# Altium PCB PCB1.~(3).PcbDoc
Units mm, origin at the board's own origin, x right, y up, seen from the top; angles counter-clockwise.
Board outline 49.47 x 17.47 mm, 4 copper layers (Top Layer, Layer 1, Layer 2, Bottom Layer), stack 0.127 mm thick; 1 components, 1 nets, 2 pads, 3 vias.
Unrouted connection lines stored in the file: 4.
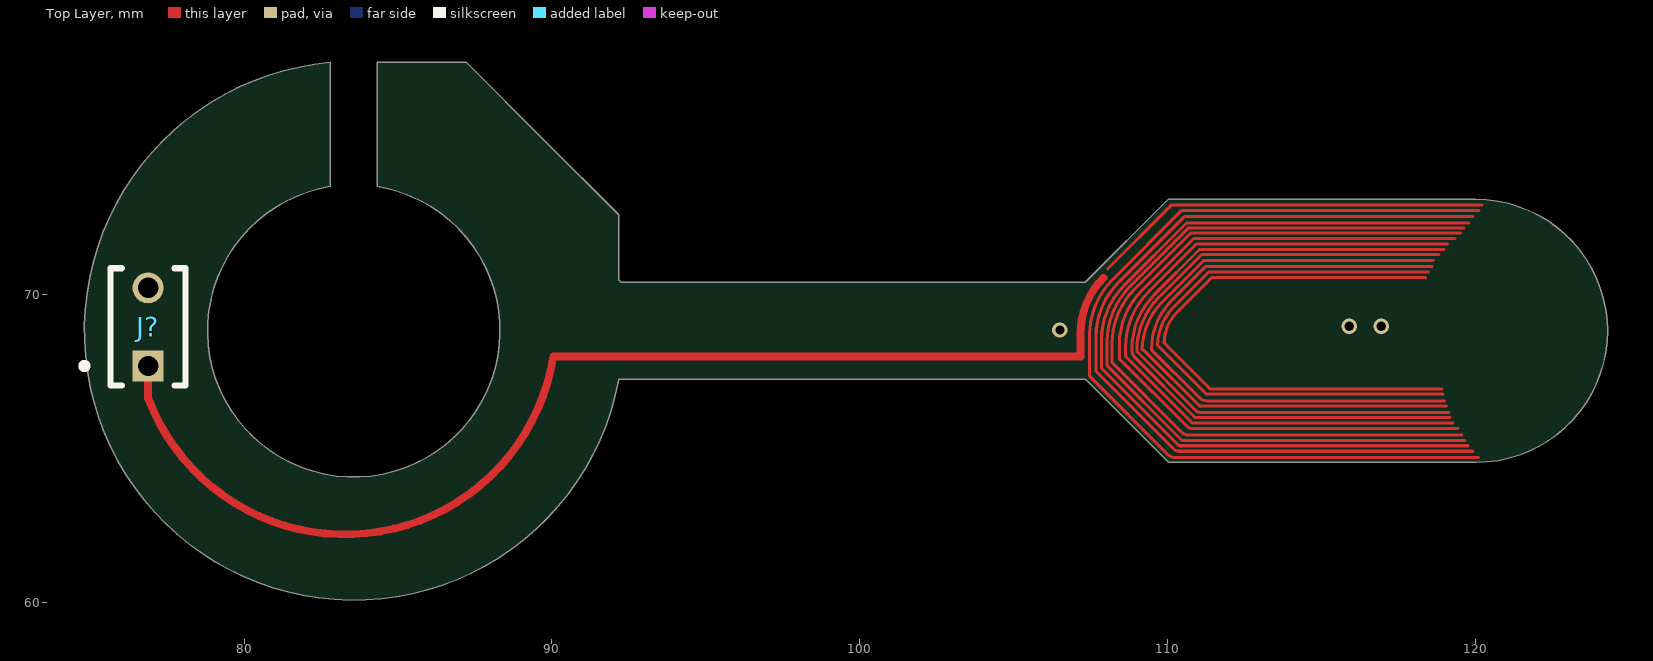
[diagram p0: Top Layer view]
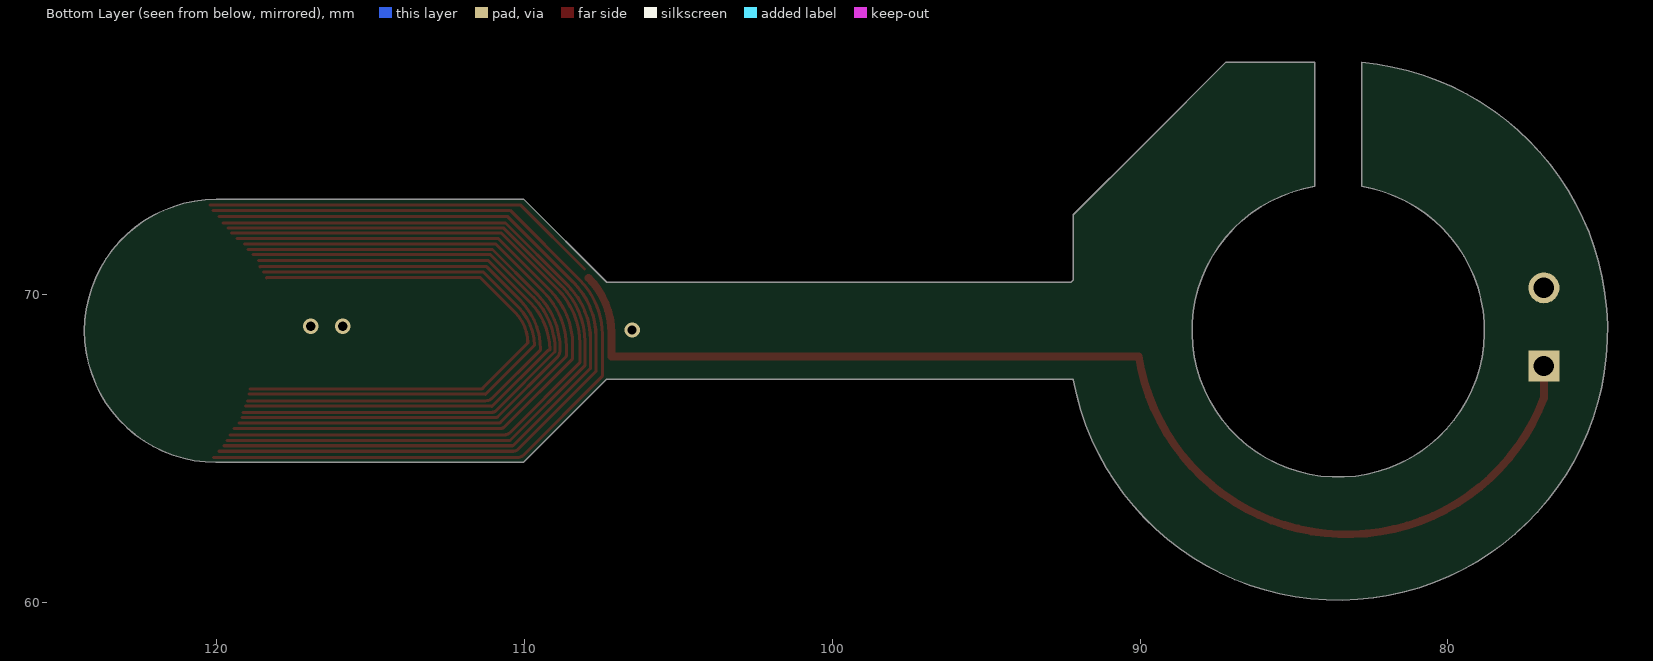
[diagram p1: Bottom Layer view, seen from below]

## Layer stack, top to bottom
Top Solder: solder mask 0.0102, Solder Resist, Dk 3.5
Top Layer: signal copper 0.0127
Dielectric 2: prepreg 0.0254, PP-006, Dk 3.5
Layer 1: signal copper 0.0127
Dielectric 1: dielectric 0.0254, FR-4, Dk 3.5
Layer 2: signal copper 0.0127
Dielectric 3: prepreg 0.0254, PP-006, Dk 3.5
Bottom Layer: signal copper 0.0127
Bottom Solder: solder mask 0.0102, Solder Resist, Dk 3.5

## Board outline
82.805,73.523 ccw(c83.566,68.834) 84.327,73.523 84.329,73.534 84.329,77.551 87.224,77.551 89.753,75.021 92.171,72.604 92.171,70.483 92.245,70.409 107.326,70.409 110.018,73.101 120.018,73.101 cw(c120.021,68.831) 120.021,64.561 120.021,64.57 110.021,64.57 107.332,67.259 92.183,67.259 92.171,67.245 cw(c83.566,68.834) 82.803,77.551

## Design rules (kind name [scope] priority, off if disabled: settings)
Clearance [All] p1: gap=0.254 ignorepadtopadclearanceinfootprint=FALSE except(0: Arc-Hole Track-Hole SMDPad-Hole THPad-Hole Via-Hole Fill-Hole Poly-Hole Region-Hole Text-Hole; 0.06: Arc-Arc Arc-Track Track-Track)
PolygonConnect [All] p1: connectstyle=Relief reliefconductorwidth=0.254 reliefentries=4 polygonreliefangle="90 Angle" airgapwidth=0.254
RoutingVias [All] p1: holewidth=0.711 width=1.27 viastyle="Through Hole" minholewidth=0.711 minwidth=1.27 maxholewidth=0.711 maxwidth=1.27
SolderMaskExpansion [All] p1: expansion=0.102 istentingtop=FALSE
Width [All] p1: maxlimit=0.254 minlimit=0.1 preferedwidth=0.1 minimp=50.000000 maximp=50.000000 favimp=50.000000
30 further rules are at their usual default settings.

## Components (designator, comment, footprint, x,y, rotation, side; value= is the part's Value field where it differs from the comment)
J? "TMS-103-59-L-S-002" SAMTEC_TMS-103-59-L-S-002 76.886,68.961 r90 top

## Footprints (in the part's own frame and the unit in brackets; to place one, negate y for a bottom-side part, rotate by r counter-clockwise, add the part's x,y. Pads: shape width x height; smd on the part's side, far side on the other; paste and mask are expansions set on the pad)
SAMTEC_TMS-103-59-L-S-002 [mm]
  rect 1.01x1.01 hole 0.66: 01(-1.27,0)
  round 1.01 hole 0.66: 03(1.27,0)
  silkscreen extent -1.91,-1.22 1.91,2.17

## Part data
J?: Package=None

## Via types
v1: diameter 0.5, hole 0.3, Top Layer to Bottom Layer, 3 vias

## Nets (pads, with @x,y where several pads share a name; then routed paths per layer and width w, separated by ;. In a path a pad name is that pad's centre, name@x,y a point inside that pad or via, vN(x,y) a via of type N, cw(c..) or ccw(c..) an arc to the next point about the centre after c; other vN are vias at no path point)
NetJ?_01: J?.01 J?.03 | length 38.8
  Top Layer w0.254: J?.01 76.886,66.648 ccw(c83.287,69.063) 90.046,68.007 ; 90.116,67.996 107.175,67.996 107.175,68.759 cw(c109.715,68.759) 107.918,70.555
  other v1: 106.502,68.859 115.9,68.986 116.942,68.986
copper on no net: | length 330.1
  Top Layer w0.1: 108.052,70.841 110.091,72.88 ccw(c110.048,72.923) 110.109,72.923 120.218,72.923 ; 118.374,70.559 118.371,70.561 111.43,70.561 110.307,69.438 ccw(c111.306,68.438) 109.893,68.438 111.354,66.977 111.354,66.967 ccw(c111.425,67.037) 111.425,66.938 118.906,66.938 ; 118.48,70.739 111.328,70.739 110.198,69.609 ccw(c111.456,68.351) 109.677,68.351 109.689,68.351 111.267,66.773 111.271,66.777 118.948,66.777 ; 118.593,70.913 118.589,70.917 111.227,70.917 110.139,69.829 ccw(c111.743,68.224) 109.474,68.224 111.049,66.65 ccw(c111.264,66.865) 111.264,66.561 119.001,66.561 ; 118.633,71.12 111.176,71.12 109.818,69.762 ccw(c111.371,68.21) 109.175,68.21 cw(c109.175,68.088) 109.261,68.174 111.058,66.377 cw(c111.092,66.343) 111.092,66.391 119.058,66.391 ; 118.822,71.308 111.1,71.308 109.72,69.928 ccw(c111.456,68.192) 109.001,68.192 ccw(c109.069,68.192) 109.021,68.144 110.923,66.242 ccw(c111.058,66.377) 111.058,66.186 119.134,66.186 ; 118.974,71.476 118.972,71.474 111.037,71.474 109.583,70.02 ccw(c111.379,68.224) 108.839,68.224 108.839,68.21 ccw(c109.175,68.21) 108.937,67.972 110.861,66.049 ccw(c110.943,66.131) 110.943,66.015 119.177,66.015 ; 119.1,71.658 110.939,71.658 109.38,70.099 ccw(c111.176,68.303) 108.636,68.303 108.636,68.047 ccw(c108.739,68.047) 108.666,67.973 110.786,65.853 ccw(c110.826,65.894) 110.826,65.837 119.278,65.837 ; 119.329,71.831 110.846,71.831 109.177,70.162 ccw(c110.973,68.366) 108.433,68.366 108.433,67.945 108.433,67.932 110.649,65.716 ccw(c110.786,65.853) 110.786,65.659 119.431,65.659 ; 119.507,72.009 110.745,72.009 108.945,70.209 ccw(c110.741,68.413) 108.201,68.413 108.201,67.818 ccw(c108.256,67.818) 108.217,67.779 110.465,65.532 ccw(c110.649,65.716) 110.649,65.456 119.558,65.456 ; 119.626,72.178 110.684,72.178 108.776,70.27 ccw(c110.572,68.474) 108.032,68.474 108.032,67.745 ccw(c108.119,67.745) 108.057,67.683 110.454,65.287 110.463,65.278 119.659,65.278 ; 119.761,65.1 110.395,65.1 cw(c110.395,65.157) 110.354,65.117 107.869,67.602 cw(c107.916,67.648) 107.85,67.648 107.85,68.52 cw(c110.39,68.52) 108.594,70.316 110.617,72.339 119.786,72.339 ; 119.913,64.922 110.354,64.922 cw(c110.354,65.117) 110.217,64.979 107.698,67.498 cw(c107.763,67.564) 107.671,67.564 107.671,68.62 cw(c110.211,68.62) 108.415,70.416 110.541,72.542 119.913,72.542 ; 120.091,64.719 110.217,64.719 cw(c110.217,64.979) 110.033,64.795 107.467,67.361 107.467,68.696 cw(c110.007,68.696) 108.211,70.492 110.465,72.746 120.117,72.746

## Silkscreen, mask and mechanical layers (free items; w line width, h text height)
Mechanical 1:
  lines w0.127: 82.803,73.534 82.803,77.551 ccw(c83.566,68.834) 92.171,67.245 ; 82.805,73.523 ccw(c83.566,68.834) 84.327,73.523 ; 84.329,73.534 84.329,77.551 87.224,77.551 89.753,75.021 92.171,72.604 92.171,70.483 92.245,70.409 107.326,70.409 110.018,73.101 120.018,73.101 cw(c120.021,68.831) 120.021,64.561 ; 92.183,67.259 107.332,67.259 110.021,64.57 120.021,64.57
